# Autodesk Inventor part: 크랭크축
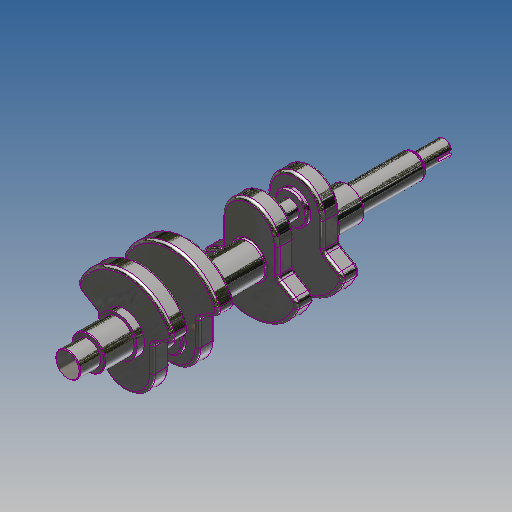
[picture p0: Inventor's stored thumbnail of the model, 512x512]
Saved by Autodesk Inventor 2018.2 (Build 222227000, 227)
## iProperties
Created: 2017-03
Part Number: 크랭크축
Material: 강철, 탄소
Document SubType Name: Modeling
Designer: mduedu
Density: 7.87 g/cm^3
Mass: 1576.89 g
Surface Area: 429.128 cm^2
Volume: 200.367 cm^3
Appearance: 반광택
Author: mduedu
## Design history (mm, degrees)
sketch "스케치1" dims "d5" = 50
  geometry: L1 (-19, 16.248)-(-19, -1.752); L2 (-19, -1.752)-(-33.503, -10.125); L3 (19, 16.248)-(19, -1.752); L4 (0, 16.248)-(0, -35); L5 (19, -1.752)-(33.503, -10.125); C1 r 8.5 at (0, 0); C2 r 13.5 at (0, 0); A1 r 35 centre (0, 0) between (-33.503, -10.125) and (0, -35); A2 r 35 centre (0, 0) between (0, -35) and (33.503, -10.125); A3 r 19 centre (0, 16.248) between (19, 16.248) and (0, 35.248); A4 r 19 centre (0, 16.248) between (0, 35.248) and (-19, 16.248); 3 further points
  constraints: 10 end point, 8 point on circle, 6 centre point, 5 coincident, 3 symmetric about line, 2 point on line, 1 parallel, 1 tangent, 1 vertical, 1 vertical alignment, 5 other
  dimensions: "d0" = 17 diameter of C1; "d1" = 27 diameter of C2; "d2" = 18 distance of L1.start L1.end; "d3" = 120 deg angle of L2 L1; "d4" = 35 radius of A1; "d6" = 19 radius of A4
extrude "돌출1" new body sketch "스케치1" distance "d7" = 12; taper "d8" = 0 deg
extrude "돌출2" join sketch "스케치1" distance "d9" = 5; taper "d10" = 0 deg
extrude "돌출3" join sketch "스케치1" distance "d11" = 90; taper "d12" = 0 deg
sketch "스케치2"
  geometry: C1 r 11 at (0, 16.248); C2 r 6 at (0, 16.248); A1 r 19 centre (0, 16.248) between (19, 16.248) and (-19, 16.248) reference; 1 further point
  constraints: 2 centre point, 2 coincident
  dimensions: "d13" = 22 diameter of C1; "d14" = 12 diameter of C2
extrude "돌출4" join sketch "스케치2" distance "d15" = 3; taper "d16" = 0 deg
extrude "돌출5" join sketch "스케치2" distance "d17" = 16; taper "d18" = 0 deg
fillet "모깎기1" dims "d19" = 3, "d20" = 5
fillet "모깎기2" dims "d21" = 2
sketch "스케치3"
  geometry: C1 r 11.5 at (0, 0); 1 further point
  constraints: 1 centre point, 1 coincident
  dimensions: "d22" = 23 diameter of C1
extrude "돌출6" join sketch "스케치3" distance "d23" = 19; taper "d24" = 0 deg
sketch "스케치4"
  geometry: C1 r 8.5 at (0, 0) reference; C2 r 5.5 at (0, 0); 1 further point
  constraints: 1 centre point
  dimensions: "d25" = 3 radial gap between concentric circles of C1 C2
extrude "돌출7" cut sketch "스케치4" distance "d26" = 20; taper "d27" = 0 deg
node "작업 평면1"
sketch "스케치5"
  geometry: L1 (-5.5, 0)-(5.5, 0) reference; L2 (-1.5, 0)-(1.5, 0); L3 (1.5, 0)-(1.5, 8.5); L4 (-1.5, 8.5)-(-1.5, 0); A1 r 1.5 centre (0, 8.5) between (1.5, 8.5) and (-1.5, 8.5); 1 further point
  constraints: 6 end point, 2 point on circle, 2 tangent, 1 centre point, 1 horizontal, 1 parallel, 1 perpendicular, 1 point on line, 1 vertical alignment
  dimensions: "d28" = 3 distance between parallel lines of L3 L4; "d30" = 10 dimension on A1 L1
extrude "돌출8" cut sketch "스케치5" distance "d31" = 1.8; taper "d32" = 0 deg
chamfer "모따기1" distance "d33" = 0.5; stored, may be unused: second distance "d34" = 2, angle "d35" = 45 deg
chamfer "모따기2" distance "d36" = 1; stored, may be unused: second distance "d37" = 2, angle "d38" = 45 deg
node "작업 평면2"
sketch "스케치6"
  geometry: C1 r 11.5 at (0, 0) reference; C2 r 11.5 at (0, 0) reference; 1 further point
extrude "돌출9" join sketch "스케치6" distance "d39" = 42; taper "d40" = 0 deg
sketch "스케치7" dims "d46" = 50
  geometry: L1 (-19, -16.248)-(-19, 1.752); L2 (19, -16.248)-(19, 1.752); L3 (-19, 1.752)-(-33.503, 10.125); L4 (19, 1.752)-(33.503, 10.125); L5 (0, -16.248)-(0, 35); C1 r 13.5 at (0, 0); C2 r 6 at (0, 0); A1 r 19 centre (0, -16.248) between (0, -35.248) and (19, -16.248); A2 r 19 centre (0, -16.248) between (-19, -16.248) and (0, -35.248); A3 r 35 centre (0, 0) between (0, 35) and (-33.503, 10.125); A4 r 35 centre (0, 0) between (33.503, 10.125) and (0, 35); 3 further points
  constraints: 10 end point, 8 point on circle, 6 centre point, 5 coincident, 3 symmetric about line, 2 point on line, 1 parallel, 1 tangent, 1 vertical, 5 other
  dimensions: "d41" = 12 diameter of C2; "d42" = 27 diameter of C1; "d43" = 18 distance of L2.start L2.end; "d44" = 120 deg angle of L4 L2; "d45" = 35 radius of A4; "d47" = 19 radius of A1
extrude "돌출10" join sketch "스케치7" distance "d48" = 12; taper "d49" = 0 deg
sketch "스케치8"
  geometry: C1 r 11 at (0, -16.248); C2 r 6 at (0, -16.248); A1 r 19 centre (0, -16.248) between (-19, -16.248) and (19, -16.248) reference; 1 further point
  constraints: 2 centre point, 2 coincident
  dimensions: "d50" = 22 diameter of C1; "d51" = 12 diameter of C2
extrude "돌출11" join sketch "스케치8" distance "d52" = 3; taper "d53" = 0 deg
extrude "돌출12" join sketch "스케치8" distance "d54" = 16; taper "d55" = 0 deg
fillet "모깎기3" dims "d56" = 3, "d57" = 5
fillet "모깎기4" dims "d58" = 2
chamfer "모따기3" distance "d59" = 1; stored, may be unused: second distance "d60" = 2, angle "d61" = 45 deg
node "작업 평면3"
fillet "모깎기5" dims "d62" = 1
sketch "스케치9"
  geometry: C1 r 13.5 at (0, 0) reference; 1 further point
extrude "돌출13" join sketch "스케치9" distance "d63" = 5; taper "d64" = 0 deg
sketch "스케치10"
  geometry: C1 r 8.5 at (0, 0) reference; C2 r 8.5 at (0, 0) reference; 1 further point
  dimensions: "d79" = 17 diameter of C1 (derived)
extrude "돌출14" join sketch "스케치10" distance "d65" = 34; taper "d66" = 0 deg
sketch "스케치11"
  geometry: C1 r 11.5 at (0, 0); 1 further point
  constraints: 1 centre point, 1 coincident
  dimensions: "d67" = 23 diameter of C1
extrude "돌출15" join sketch "스케치11" distance "d68" = 20; taper "d69" = 0 deg
chamfer "모따기4" distance "d70" = 0.5; stored, may be unused: second distance "d71" = 2, angle "d72" = 45 deg
sketch "스케치12"
  geometry: L1 (8.5, -70)-(-8.5, -70) reference; L2 (-8.5, -24)-(-8.5, -70) reference; L3 (-7.45, -70)-(-8.5, -68.181); L4 (5, -90)-(-5, -90) reference; L5 (0, -90)-(0, -70); 3 further points
  constraints: 4 end point, 2 midpoint, 2 point on line
  dimensions: "d80" = 14.9 diameter of L3.start L5; "d81" = 30 deg angle of L2 L3
revolve "회전1" sketch "스케치12" stored, may be unused: angle "d82" = 90 deg
fillet "모깎기7" dims "d83" = 2, "d84" = 1
node "솔리드1"
mirror "대칭1"
mirror "대칭2"
node "투영된 루프1"
node "투영된 루프2"
